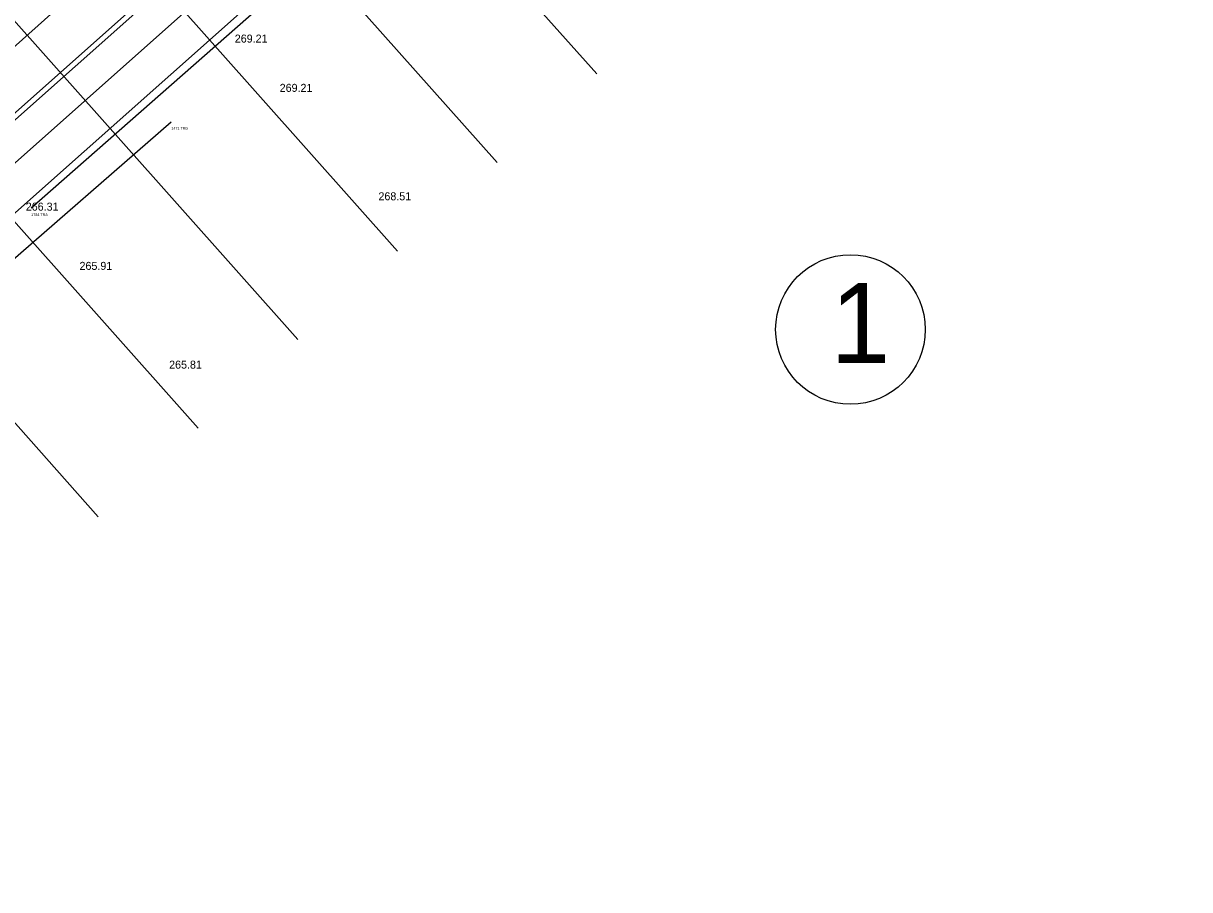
# Model space of a CAD drawing. Extents: x 49683 to 58852, y 49525 to 54803.
# Drawn here: x 55722.8 to 56160.2, y 53172.6 to 53497.5 of the extents above; entities that cross this region are included whole.
import ezdxf

# ---------------------------------------------------------------- set-up
doc = ezdxf.new("R2010")
doc.units = 0
for name, color, linetype in [('Level 11', 7, 'Continuous'), ('Level 13', 7, 'Continuous'), ('Level 19', 7, 'Continuous'), ('Level 20', 7, 'Continuous'), ('Level 25', 7, 'Continuous'), ('Level 3', 7, 'Continuous'), ('Level 32', 7, 'Continuous'), ('Level 50', 7, 'Continuous'), ('Level 61', 7, 'Continuous'), ('Level 63', 7, 'Continuous')]:
    doc.layers.add(name, color=color, linetype=linetype)

msp = doc.modelspace()

# ---------------------------------------------------------------- linework, layer by layer
at = {"layer": 'Level 11'}
for p, q in [((55725.8, 53428.27), (55939.67, 53616.48)), ((55479.23, 53199.92), (55778.33, 53460.62))]:
    msp.add_line(p, q, dxfattribs=at)
at = {"layer": 'Level 13'}
msp.add_line((55556.51, 53316.2), (56052.34, 53756.94), dxfattribs=at)
at = {"layer": 'Level 19'}
msp.add_line((54181.77, 52078.16), (56150.85, 53828.45), dxfattribs=at)
at = {"layer": 'Level 20'}
for p, q in [((54172.47, 52088.62), (56141.55, 53838.91)), ((54191.07, 52067.7), (56160.15, 53817.98))]:
    msp.add_line(p, q, dxfattribs=at)
at = {"layer": 'Level 25'}
msp.add_circle((56032.96, 53382.69), 28.04, dxfattribs=at)
at = {"layer": 'Level 3'}
msp.add_line((55745.53, 53512.03), (55712.65, 53482.7), dxfattribs=at)
at = {"layer": 'Level 50'}
for p, q in [((55778.37, 53657.91), (55937.82, 53478.53)), ((55741, 53624.69), (55900.45, 53445.31)), ((55703.63, 53591.47), (55863.08, 53412.1)), ((55666.26, 53558.26), (55825.71, 53378.88)), ((55628.89, 53525.04), (55788.34, 53345.66)), ((55591.52, 53491.82), (55750.97, 53312.44))]:
    msp.add_line(p, q, dxfattribs=at)
at = {"layer": 'Level 63'}
for p, q in [((54181.77, 52078.16), (56092.55, 53776.62)), ((56101.85, 53766.16), (54191.07, 52067.7)), ((56008.51, 53720.65), (54172.47, 52088.62)), ((54181.77, 52078.16), (56017.81, 53710.19))]:
    msp.add_line(p, q, dxfattribs=at)

# ---------------------------------------------------------------- texts
at = {"layer": 'Level 25'}
msp.add_text('1', height=30, dxfattribs=at).set_placement((56025.54, 53370.15))
at = {"layer": 'Level 32'}
for s, p in [('269.21', (55802.13, 53490.3)), ('269.21', (55818.97, 53471.82)), ('268.51', (55856, 53431.15)), ('266.31', (55723.77, 53427.26)), ('265.91', (55743.92, 53405.04)), ('265.81', (55777.52, 53368))]:
    msp.add_text(s, height=3, dxfattribs=at).set_placement(p)
at = {"layer": 'Level 61'}
for s, p in [('1471 TRB', (55778.33, 53457.62)), ('1784 TRA ', (55725.8, 53425.27))]:
    msp.add_text(s, height=1, dxfattribs=at).set_placement(p)

doc.saveas('drawing.dxf')
